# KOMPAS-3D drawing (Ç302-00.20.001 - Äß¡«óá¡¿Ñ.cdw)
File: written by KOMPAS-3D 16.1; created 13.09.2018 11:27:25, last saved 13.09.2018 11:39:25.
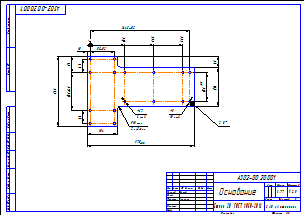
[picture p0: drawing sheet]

Sheet 1: A3, landscape

Title block, sheet 1: name: Основание; designation: А302-00.20.001; material: Сталь 20  ГОСТ 1050-2013; mass: 3,77; scale: 1:2,5; sheets: 1; organisation: ЗАО «Астерион»; sheet format: A3; stored path: Z:\Мембранные насосы\Мембранный электропривод\А302-00.00.000 - ASTRA-302 (МЭ200)\3Д\А302-00.20.001 - Основание.cdw; drawn by: Милов; technical control: Лучихин

Views: Вид 1, Спереди
Referenced files in Z:\Мембранные насосы\Мембранный электропривод\А302-00.00.000 - ASTRA-302 (МЭ200)\3Д\: А302-00.20.001 - Основание-1.m3d
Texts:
  max
Dimensions and other numbers on the sheet: 85±0,2; 130±0,2; 46; 57; 47; 100; 344,5±0,2; 120; 220; 320; 40; 134; 243; 10; 104; 370; 6,7; 6 отв.; 8; 10 отв.; 2 радиуса; 1:2,5; 1; 3,77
